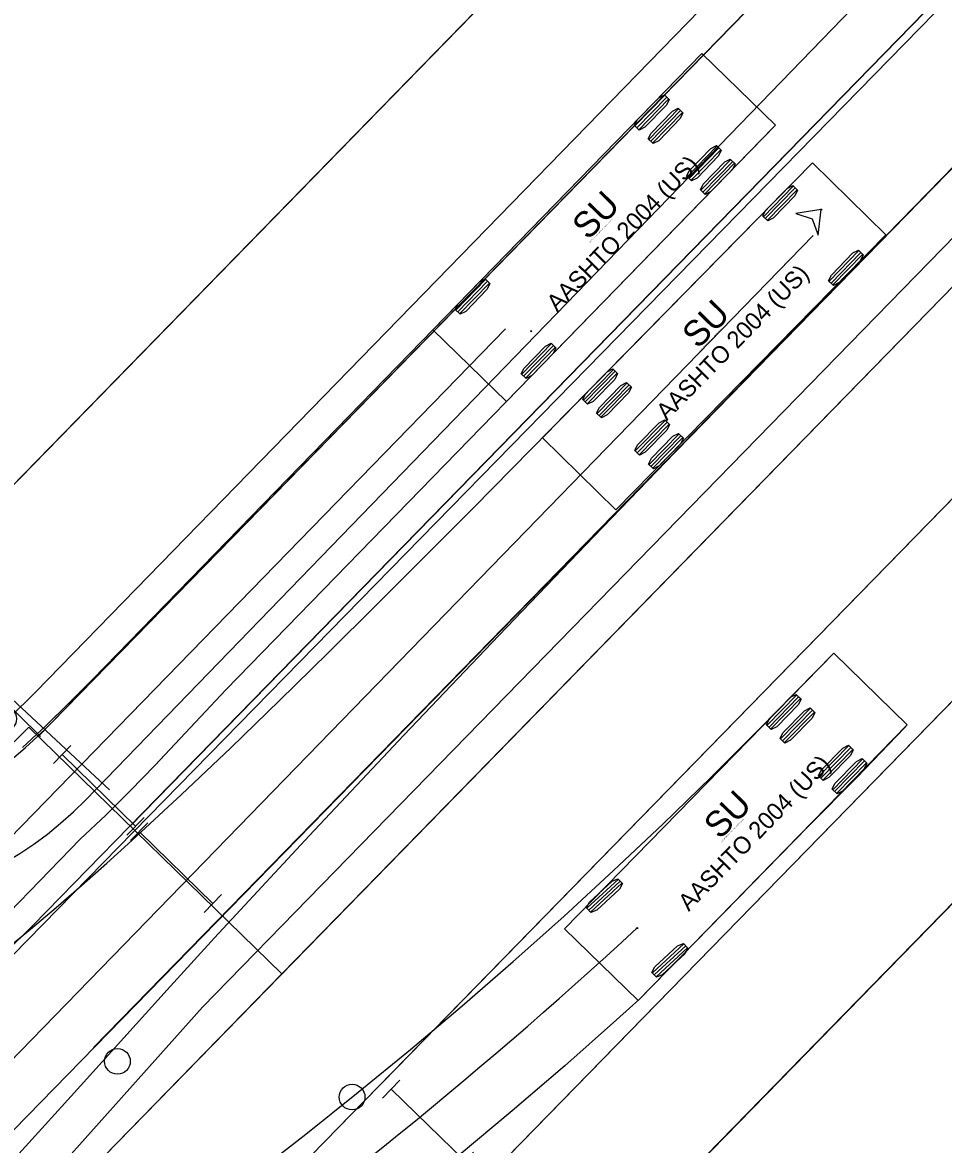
# Model space of a CAD drawing. Extents: x 2252379 to 2256472, y 13788212 to 13792539.
# Drawn here: x 2255483.2 to 2255554.9, y 13791367.7 to 13791455 of the extents above; entities that cross this region are included whole.
import ezdxf

# ---------------------------------------------------------------- set-up
doc = ezdxf.new("R2010")
doc.units = 0
for name, color, linetype in [('D_TCP_OVERALL_PATT', 7, 'Continuous'), ('D_TCP_PH_1_ATVEHICLE', 7, 'Continuous'), ('D_TCP_PH_1_BARRIER', 7, 'Continuous'), ('D_TCP_PH_1_PATT', 7, 'Continuous'), ('D_TCP_PH_1_TEMP_PVMNT', 7, 'Continuous'), ('D_TCP_PH_1_WZPM_NRMV_4IN_W_SLD', 7, 'Continuous'), ('D_TCP_PH_1_WZPM_RMV_4IN_Y_SLD', 7, 'Continuous'), ('D_TCP_PH_1A_ATVEHICLE', 7, 'Continuous'), ('D_TCP_PH_1A_BARREL', 7, 'Continuous'), ('D_TCP_PH_1A_PATT', 7, 'Continuous'), ('D_TCP_PH_1A_WZPM_NRMV_4IN_W_SLD', 7, 'Continuous'), ('D_TCP_PH_1A_WZPM_RMV_4IN_Y_SLD', 7, 'Continuous'), ('D_TCP_PH_1B_BARREL', 7, 'Continuous'), ('D_TCP_PH_1B_PATT', 7, 'Continuous'), ('D_TCP_PH_1B_WZPM_NRMV_4IN_W_SLD', 7, 'Continuous'), ('D_TCP_PH_1B_WZPM_RMV_4IN_Y_SLD', 7, 'Continuous'), ('D_TCP_PH_2_BARREL', 7, 'Continuous'), ('D_TCP_PH_2_MISC', 7, 'Continuous'), ('D_TCP_PH_2_SIGN', 7, 'Continuous'), ('D_TCP_PH_2_WZPM_NRMV_4IN_W_SLD', 7, 'Continuous'), ('D_TCP_PH_2_WZPM_NRMV_4IN_Y_SLD', 7, 'Continuous'), ('D_TCP_PH_2A_MISC', 7, 'Continuous'), ('D_TCP_PH_2A_WZPM_NRMV_4IN_W_SLD', 7, 'Continuous'), ('D_TCP_PH_2A_WZPM_RMV_4IN_Y_SLD', 7, 'Continuous'), ('E_Structure_Sign_Sign And Post Single_SGN', 7, 'Continuous'), ('Geom_Centerline', 7, 'Continuous'), ('Level 1', 7, 'Continuous'), ('z - Construction', 7, 'Continuous')]:
    doc.layers.add(name, color=color, linetype=linetype)

# ---------------------------------------------------------------- blocks, each defined once
blk = doc.blocks.new('TYP3')
at = {"layer": 'Level 1'}
for p, q in [((-0.1651, 0.0395), (-0.1651, -0.0395)), ((0.163, 0.0395), (0.163, -0.0395)), ((0.163, 0), (-0.163, 0))]:
    blk.add_line(p, q, dxfattribs=at)
blk = doc.blocks.new('SGN')
at = {"layer": 'E_Structure_Sign_Sign And Post Single_SGN'}
blk.add_line((0.6, -0.2), (-0.6, -0.2), dxfattribs=at)
for radius in [0.2, 0.137, 0.0611]:
    blk.add_circle((0, 0), radius, dxfattribs=at)

msp = doc.modelspace()

# ---------------------------------------------------------------- linework, layer by layer
at = {"layer": 'D_TCP_OVERALL_PATT'}
for p, q in [((2255692.066, 13791633.917), (2255472.331, 13791408.605)), ((2255721.86, 13791604.845), (2255480.337, 13791357.304)), ((2255483.407, 13791360.45), (2255721.86, 13791604.845)), ((2255503.412, 13791380.953), (2255721.86, 13791604.845)), ((2255503.412, 13791380.953), (2255483.728, 13791400.16)), ((2255503.412, 13791380.953), (2255483.728, 13791400.16)), ((2255483.728, 13791400.16), (2255503.412, 13791380.953)), ((2255483.407, 13791360.45), (2255503.412, 13791380.953))]:
    msp.add_line(p, q, dxfattribs=at)
msp.add_lwpolyline([(2255692.066, 13791633.917), (2255473.668, 13791409.976), (2255472.331, 13791408.605)], dxfattribs=at)
msp.add_arc((2255462.257, 13791421.113), 30, 227.75639, 315.70035, dxfattribs=at)
msp.add_arc((2255462.257, 13791421.113), 30, 227.75639, 315.70035, dxfattribs=at)
msp.add_arc((2255462.257, 13791421.113), 30, 227.75639, 315.70035, dxfattribs=at)
at = {"layer": 'D_TCP_PH_1_ATVEHICLE'}
for p, q in [((2255536.092, 13791452.618), (2255515.17, 13791431.117)), ((2255541.825, 13791447.039), (2255536.092, 13791452.618)), ((2255530.894, 13791446.978), (2255533.219, 13791449.367)), ((2255531.044, 13791446.833), (2255533.368, 13791449.222)), ((2255531.193, 13791446.687), (2255533.517, 13791449.076)), ((2255531.969, 13791445.932), (2255534.294, 13791448.321)), ((2255532.119, 13791445.787), (2255534.443, 13791448.176)), ((2255532.268, 13791445.641), (2255534.593, 13791448.03)), ((2255520.903, 13791425.538), (2255541.825, 13791447.039)), ((2255534.955, 13791443.026), (2255537.28, 13791445.415)), ((2255535.105, 13791442.881), (2255537.429, 13791445.27)), ((2255535.254, 13791442.736), (2255537.579, 13791445.124)), ((2255536.03, 13791441.98), (2255538.355, 13791444.369)), ((2255544.706, 13791444.109), (2255523.695, 13791422.696)), ((2255536.18, 13791441.835), (2255538.504, 13791444.224)), ((2255536.329, 13791441.689), (2255538.654, 13791444.078)), ((2255550.416, 13791438.506), (2255544.706, 13791444.109)), ((2255544.706, 13791444.109), (2255544.706, 13791444.109)), ((2255543.213, 13791442.301), (2255540.89, 13791439.911)), ((2255543.362, 13791442.156), (2255541.039, 13791439.766)), ((2255543.512, 13791442.011), (2255541.189, 13791439.62)), ((2255477.825, 13791369.572), (2255544.76, 13791438.453)), ((2255529.405, 13791417.093), (2255550.416, 13791438.506)), ((2255548.331, 13791437.285), (2255546.008, 13791434.894)), ((2255548.48, 13791437.14), (2255546.157, 13791434.749)), ((2255548.63, 13791436.994), (2255546.307, 13791434.604)), ((2255516.946, 13791432.644), (2255519.271, 13791435.033)), ((2255517.096, 13791432.499), (2255519.42, 13791434.888)), ((2255517.245, 13791432.354), (2255519.57, 13791434.743)), ((2255520.826, 13791431.194), (2255478.972, 13791388.183)), ((2255515.17, 13791431.117), (2255520.903, 13791425.538)), ((2255522.083, 13791427.646), (2255524.407, 13791430.035)), ((2255522.232, 13791427.501), (2255524.557, 13791429.89)), ((2255522.381, 13791427.356), (2255524.706, 13791429.745)), ((2255529.213, 13791428.022), (2255526.879, 13791425.643)), ((2255529.362, 13791427.876), (2255527.027, 13791425.497)), ((2255529.511, 13791427.73), (2255527.176, 13791425.351)), ((2255530.284, 13791426.972), (2255527.949, 13791424.592)), ((2255530.433, 13791426.826), (2255528.098, 13791424.447)), ((2255530.581, 13791426.68), (2255528.247, 13791424.301)), ((2255520.903, 13791425.538), (2255520.903, 13791425.538)), ((2255533.258, 13791424.053), (2255530.923, 13791421.674)), ((2255533.407, 13791423.908), (2255531.072, 13791421.528)), ((2255533.555, 13791423.762), (2255531.221, 13791421.382)), ((2255523.695, 13791422.696), (2255529.405, 13791417.093)), ((2255534.329, 13791423.003), (2255531.994, 13791420.624)), ((2255534.477, 13791422.857), (2255532.143, 13791420.478)), ((2255534.626, 13791422.711), (2255532.291, 13791420.332))]:
    msp.add_line(p, q, dxfattribs=at)
for points in [[(2255483.217, 13791398.586), (2255485.035, 13791400.276), (2255486.859, 13791402.059), (2255488.69, 13791403.909), (2255536.092, 13791452.618), (2255541.825, 13791447.039), (2255541.67, 13791446.879), (2255541.67, 13791446.879)], [(2255541.67, 13791446.879), (2255499.047, 13791403.066), (2255493.519, 13791397.188), (2255491.631, 13791395.232), (2255489.698, 13791393.311), (2255487.72, 13791391.437), (2255479.036, 13791382.513)], [(2255481.858, 13791382.799), (2255483.857, 13791384.45), (2255485.843, 13791386.134), (2255487.815, 13791387.849), (2255489.775, 13791389.588), (2255491.723, 13791391.351), (2255495.592, 13791394.93), (2255499.428, 13791398.569), (2255503.239, 13791402.252), (2255507.028, 13791405.969), (2255510.802, 13791409.712), (2255518.315, 13791417.252), (2255525.797, 13791424.84), (2255544.706, 13791444.109), (2255550.416, 13791438.506), (2255535.373, 13791422.973), (2255527.695, 13791415.013), (2255520.289, 13791407.297), (2255512.899, 13791399.538), (2255505.53, 13791391.707), (2255501.852, 13791387.75), (2255498.174, 13791383.756), (2255494.488, 13791379.715), (2255487.019, 13791371.447), (2255482.179, 13791366.124)], [(2255545.386, 13791440.463), (2255543.407, 13791440.174), (2255544.689, 13791439.746), (2255545.154, 13791438.477), (2255545.386, 13791440.463)]]:
    msp.add_lwpolyline(points, dxfattribs=at)
for points in [[(2255531.23, 13791446.651), (2255530.857, 13791447.014), (2255531.07, 13791447.458), (2255532.744, 13791449.178), (2255533.182, 13791449.403), (2255533.555, 13791449.04), (2255533.341, 13791448.597), (2255531.668, 13791446.877)], [(2255532.305, 13791445.605), (2255531.932, 13791445.968), (2255532.145, 13791446.412), (2255533.819, 13791448.132), (2255534.257, 13791448.357), (2255534.63, 13791447.994), (2255534.416, 13791447.551), (2255532.743, 13791445.83)], [(2255535.291, 13791442.699), (2255534.918, 13791443.062), (2255535.132, 13791443.506), (2255536.805, 13791445.226), (2255537.243, 13791445.451), (2255537.616, 13791445.088), (2255537.403, 13791444.645), (2255535.729, 13791442.925)], [(2255536.366, 13791441.653), (2255535.993, 13791442.016), (2255536.207, 13791442.46), (2255537.88, 13791444.18), (2255538.318, 13791444.405), (2255538.691, 13791444.042), (2255538.478, 13791443.599), (2255536.804, 13791441.879)], [(2255543.176, 13791442.337), (2255543.549, 13791441.975), (2255543.336, 13791441.531), (2255541.663, 13791439.81), (2255541.226, 13791439.584), (2255540.853, 13791439.947), (2255541.066, 13791440.391), (2255542.738, 13791442.112)], [(2255545.386, 13791440.463), (2255543.407, 13791440.174), (2255544.689, 13791439.746), (2255545.154, 13791438.477)], [(2255548.294, 13791437.321), (2255548.667, 13791436.958), (2255548.454, 13791436.515), (2255546.781, 13791434.793), (2255546.344, 13791434.568), (2255545.971, 13791434.93), (2255546.184, 13791435.374), (2255547.856, 13791437.095)], [(2255517.282, 13791432.318), (2255516.909, 13791432.68), (2255517.123, 13791433.124), (2255518.796, 13791434.844), (2255519.234, 13791435.069), (2255519.607, 13791434.707), (2255519.393, 13791434.263), (2255517.72, 13791432.543)], [(2255522.418, 13791427.32), (2255522.046, 13791427.682), (2255522.259, 13791428.126), (2255523.933, 13791429.846), (2255524.37, 13791430.071), (2255524.743, 13791429.709), (2255524.53, 13791429.265), (2255522.856, 13791427.545)], [(2255529.176, 13791428.058), (2255529.547, 13791427.694), (2255529.332, 13791427.251), (2255527.652, 13791425.538), (2255527.213, 13791425.315), (2255526.842, 13791425.679), (2255527.057, 13791426.122), (2255528.738, 13791427.835)], [(2255530.247, 13791427.008), (2255530.618, 13791426.644), (2255530.403, 13791426.201), (2255528.722, 13791424.488), (2255528.284, 13791424.264), (2255527.912, 13791424.629), (2255528.127, 13791425.071), (2255529.808, 13791426.785)], [(2255533.221, 13791424.09), (2255533.592, 13791423.725), (2255533.377, 13791423.283), (2255531.696, 13791421.57), (2255531.258, 13791421.346), (2255530.886, 13791421.71), (2255531.101, 13791422.153), (2255532.782, 13791423.866)], [(2255534.292, 13791423.039), (2255534.663, 13791422.675), (2255534.448, 13791422.232), (2255532.767, 13791420.519), (2255532.328, 13791420.296), (2255531.957, 13791420.66), (2255532.172, 13791421.103), (2255533.853, 13791422.816)]]:
    msp.add_lwpolyline(points, close=True, dxfattribs=at)
for centre in [(2255545.386, 13791440.463), (2255522.817, 13791430.998)]:
    msp.add_circle(centre, 0.0417, dxfattribs=at)
at = {"layer": 'D_TCP_PH_1_BARRIER'}
for p, q in [((2255497.239, 13791378.38), (2255720.621, 13791607.51)), ((2255483.913, 13791363.467), (2255497.239, 13791378.38))]:
    msp.add_line(p, q, dxfattribs=at)
at = {"layer": 'D_TCP_PH_1_PATT'}
msp.add_line((2255721.86, 13791604.845), (2255480.337, 13791357.304), dxfattribs=at)
at = {"layer": 'D_TCP_PH_1_TEMP_PVMNT'}
for p, q in [((2255488.147, 13791394.516), (2255793.369, 13791709.822)), ((2255701.252, 13791625.9), (2255484.24, 13791402.883))]:
    msp.add_line(p, q, dxfattribs=at)
for centre, radius, start, end in [((2255459.416, 13791427.038), 34.637, 266.30548, 315.78176), ((2255467.824, 13791414.265), 28.337, 232.25583, 315.82092)]:
    msp.add_arc(centre, radius, start, end, dxfattribs=at)
at = {"layer": 'D_TCP_PH_1_WZPM_NRMV_4IN_W_SLD'}
for p, q in [((2255485.246, 13791400.284), (2255664.146, 13791583.612)), ((2255488.749, 13791375.238), (2255678.46, 13791569.644))]:
    msp.add_line(p, q, dxfattribs=at)
msp.add_arc((2255461.628, 13791423.332), 33, 248.71476, 315.70035, dxfattribs=at)
at = {"layer": 'D_TCP_PH_1_WZPM_RMV_4IN_Y_SLD'}
msp.add_line((2255484.04, 13791384.73), (2255671.303, 13791576.628), dxfattribs=at)
msp.add_arc((2255455.412, 13791412.667), 40, 224.52752, 315.70035, dxfattribs=at)
at = {"layer": 'D_TCP_PH_1A_ATVEHICLE'}
for p, q in [((2255546.364, 13791405.936), (2255525.412, 13791384.464)), ((2255552.09, 13791400.349), (2255546.364, 13791405.936)), ((2255541.159, 13791400.303), (2255543.487, 13791402.689)), ((2255541.308, 13791400.157), (2255543.636, 13791402.543)), ((2255541.457, 13791400.012), (2255543.785, 13791402.398)), ((2255542.232, 13791399.255), (2255544.56, 13791401.641)), ((2255542.381, 13791399.11), (2255544.709, 13791401.496)), ((2255542.53, 13791398.964), (2255544.858, 13791401.35)), ((2255531.138, 13791378.877), (2255552.09, 13791400.349)), ((2255545.214, 13791396.345), (2255547.542, 13791398.731)), ((2255545.364, 13791396.2), (2255547.692, 13791398.586)), ((2255545.513, 13791396.054), (2255547.841, 13791398.44)), ((2255546.288, 13791395.298), (2255548.616, 13791397.684)), ((2255546.437, 13791395.152), (2255548.765, 13791397.538)), ((2255546.586, 13791395.007), (2255548.914, 13791397.393)), ((2255527.154, 13791386.074), (2255529.604, 13791388.334)), ((2255527.295, 13791385.921), (2255529.745, 13791388.181)), ((2255527.436, 13791385.768), (2255529.886, 13791388.028)), ((2255525.412, 13791384.464), (2255531.138, 13791378.877)), ((2255532.253, 13791381.038), (2255534.701, 13791383.3)), ((2255532.394, 13791380.885), (2255534.842, 13791383.147)), ((2255532.535, 13791380.732), (2255534.984, 13791382.994)), ((2255531.138, 13791378.877), (2255531.138, 13791378.877))]:
    msp.add_line(p, q, dxfattribs=at)
for points in [[(2255503.061, 13791366.774), (2255505.277, 13791368.494), (2255509.354, 13791371.746), (2255513.424, 13791375.086), (2255517.447, 13791378.482), (2255521.422, 13791381.933), (2255525.349, 13791385.44), (2255529.227, 13791389), (2255533.055, 13791392.614), (2255536.833, 13791396.281), (2255540.566, 13791400.005), (2255546.364, 13791405.936), (2255552.09, 13791400.349), (2255551.879, 13791400.126), (2255551.879, 13791400.126)], [(2255551.879, 13791400.126), (2255548.152, 13791396.25), (2255544.384, 13791392.438), (2255531.217, 13791378.958), (2255529.471, 13791377.376), (2255525.432, 13791373.813), (2255521.344, 13791370.306), (2255517.207, 13791366.856)]]:
    msp.add_lwpolyline(points, dxfattribs=at)
for points in [[(2255541.494, 13791399.976), (2255541.122, 13791400.339), (2255541.335, 13791400.782), (2255543.012, 13791402.5), (2255543.45, 13791402.725), (2255543.822, 13791402.362), (2255543.608, 13791401.918), (2255541.932, 13791400.2)], [(2255542.567, 13791398.928), (2255542.195, 13791399.291), (2255542.409, 13791399.735), (2255544.085, 13791401.453), (2255544.523, 13791401.677), (2255544.895, 13791401.314), (2255544.682, 13791400.871), (2255543.005, 13791399.153)], [(2255545.55, 13791396.018), (2255545.177, 13791396.382), (2255545.391, 13791396.825), (2255547.067, 13791398.543), (2255547.505, 13791398.767), (2255547.878, 13791398.404), (2255547.664, 13791397.961), (2255545.988, 13791396.243)], [(2255546.623, 13791394.971), (2255546.251, 13791395.334), (2255546.465, 13791395.777), (2255548.141, 13791397.495), (2255548.579, 13791397.72), (2255548.951, 13791397.357), (2255548.737, 13791396.913), (2255547.061, 13791395.195)], [(2255527.471, 13791385.73), (2255527.118, 13791386.112), (2255527.355, 13791386.544), (2255529.12, 13791388.171), (2255529.569, 13791388.372), (2255529.921, 13791387.99), (2255529.685, 13791387.558), (2255527.92, 13791385.931)], [(2255532.57, 13791380.694), (2255532.217, 13791381.076), (2255532.454, 13791381.507), (2255534.217, 13791383.136), (2255534.666, 13791383.338), (2255535.019, 13791382.956), (2255534.782, 13791382.524), (2255533.019, 13791380.895)]]:
    msp.add_lwpolyline(points, close=True, dxfattribs=at)
msp.add_circle((2255531.069, 13791384.533), 0.0417, dxfattribs=at)
msp.add_arc((2255271.348, 13791665.9), 382.912, 304.88688, 312.70909, dxfattribs=at)
at = {"layer": 'D_TCP_PH_1A_BARREL'}
msp.add_circle((2255508.882, 13791371.37), 1, dxfattribs=at)
msp.add_circle((2255508.882, 13791371.37), 1, dxfattribs=at)
at = {"layer": 'D_TCP_PH_1A_PATT'}
for p, q in [((2255692.066, 13791633.917), (2255473.668, 13791409.976)), ((2255503.412, 13791380.953), (2255721.86, 13791604.845)), ((2255483.728, 13791400.16), (2255503.412, 13791380.953))]:
    msp.add_line(p, q, dxfattribs=at)
msp.add_arc((2255462.257, 13791421.113), 30, 227.75639, 315.70035, dxfattribs=at)
at = {"layer": 'D_TCP_PH_1A_WZPM_NRMV_4IN_W_SLD'}
for p, q in [((2255511.265, 13791372.533), (2255729.301, 13791595.987)), ((2255516.791, 13791346.696), (2255746.093, 13791581.695))]:
    msp.add_line(p, q, dxfattribs=at)
at = {"layer": 'D_TCP_PH_1A_WZPM_RMV_4IN_Y_SLD'}
msp.add_line((2255508.918, 13791354.378), (2255737.697, 13791588.841), dxfattribs=at)
at = {"layer": 'D_TCP_PH_1B_BARREL'}
msp.add_circle((2255508.882, 13791371.37), 1, dxfattribs=at)
at = {"layer": 'D_TCP_PH_1B_PATT'}
for p, q in [((2255503.412, 13791380.953), (2255483.728, 13791400.16)), ((2255483.407, 13791360.45), (2255503.412, 13791380.953))]:
    msp.add_line(p, q, dxfattribs=at)
msp.add_arc((2255462.257, 13791421.113), 30, 227.75639, 315.70035, dxfattribs=at)
at = {"layer": 'D_TCP_PH_1B_WZPM_NRMV_4IN_W_SLD'}
for p, q in [((2255501.045, 13791362.06), (2255729.301, 13791595.987)), ((2255516.791, 13791346.696), (2255746.093, 13791581.695))]:
    msp.add_line(p, q, dxfattribs=at)
at = {"layer": 'D_TCP_PH_1B_WZPM_RMV_4IN_Y_SLD'}
msp.add_line((2255508.918, 13791354.378), (2255737.697, 13791588.841), dxfattribs=at)
at = {"layer": 'D_TCP_PH_2_BARREL'}
msp.add_circle((2255490.613, 13791374.148), 1, dxfattribs=at)
at = {"layer": 'D_TCP_PH_2_WZPM_NRMV_4IN_W_SLD'}
msp.add_line((2255484.456, 13791399.447), (2255615.6, 13791533.85), dxfattribs=at)
msp.add_lwpolyline([(2255420.402, 13791305.163), (2255629.915, 13791519.883)], dxfattribs=at)
at = {"layer": 'D_TCP_PH_2_WZPM_NRMV_4IN_Y_SLD'}
msp.add_line((2255491.603, 13791392.453), (2255622.757, 13791526.866), dxfattribs=at)
at = {"layer": 'D_TCP_PH_2A_WZPM_NRMV_4IN_W_SLD'}
for points in [[(2255507.699, 13791368.87), (2255642.782, 13791507.309)], [(2255449.015, 13791277.226), (2255658.528, 13791491.945)]]:
    msp.add_lwpolyline(points, dxfattribs=at)
at = {"layer": 'D_TCP_PH_2A_WZPM_RMV_4IN_Y_SLD'}
msp.add_lwpolyline([(2255515.572, 13791361.188), (2255650.655, 13791499.627)], dxfattribs=at)
at = {"layer": 'Geom_Centerline'}
msp.add_line((2255474.316, 13791374.097), (2255584.953, 13791487.208), dxfattribs=at)
at = {"layer": 'z - Construction'}
msp.add_line((2255471.812, 13791412.21), (2255490, 13791395.289), dxfattribs=at)

# ---------------------------------------------------------------- block references
at = {"layer": 'D_TCP_PH_2_MISC', "xscale": 24.384167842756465, "yscale": 24.384167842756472, "rotation": -44.28207184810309}
msp.add_blockref('TYP3', (2255514.799, 13791369.175), dxfattribs=at)
at = {"layer": 'D_TCP_PH_2_SIGN', "xscale": 5.000000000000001, "yscale": -5.000000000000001, "rotation": -44.222909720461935}
msp.add_blockref('SGN', (2255481.784, 13791400.822), dxfattribs=at)
at = {"layer": 'D_TCP_PH_2A_MISC', "xscale": 24.384167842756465, "yscale": 24.384167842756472, "rotation": -44.28207184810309}
for p in [(2255489.183, 13791395.23), (2255495.189, 13791389.214)]:
    msp.add_blockref('TYP3', p, dxfattribs=at)

# ---------------------------------------------------------------- texts
at = {"layer": 'D_TCP_PH_1_ATVEHICLE'}
for s, height, rotation, p in [('AASHTO 2004 (US)', 1.33333, 45.78176, (2255524.838, 13791432.44)), ('SU', 2, 45.78176, (2255527.254, 13791438.029)), ('(c) 2020 Transoft Solutions, Inc. All rights reserved.', 0.08, 45.78176, (2255527.384, 13791437.876)), ('AASHTO 2004 (US)', 1.33333, 45.543, (2255533.369, 13791423.978)), ('SU', 2, 45.543, (2255535.807, 13791429.557)), ('(c) 2020 Transoft Solutions, Inc. All rights reserved.', 0.08, 45.543, (2255535.937, 13791429.404))]:
    msp.add_text(s, height=height, rotation=rotation, dxfattribs=at).set_placement(p)
at = {"layer": 'D_TCP_PH_1A_ATVEHICLE'}
for s, height, p in [('AASHTO 2004 (US)', 1.33333, (2255535.082, 13791385.773)), ('SU', 2, (2255537.506, 13791391.359)), ('(c) 2020 Transoft Solutions, Inc. All rights reserved.', 0.08, (2255537.636, 13791391.206))]:
    msp.add_text(s, height=height, rotation=45.70308, dxfattribs=at).set_placement(p)

doc.saveas('drawing.dxf')
